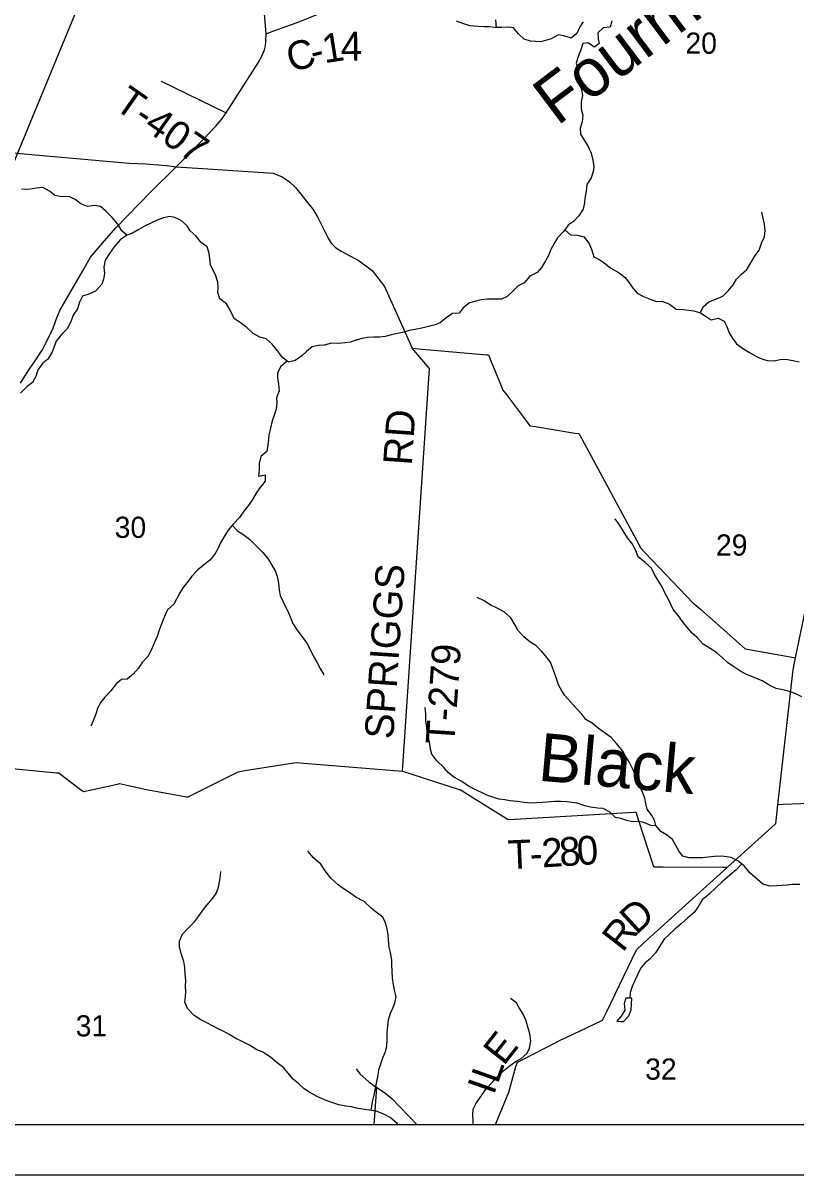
# Model space of a CAD drawing. Extents: x 0 to 34, y 0 to 22.
# Drawn here: x 4.889 to 6.417, y 14 to 16.276 of the extents above; entities that cross this region are included whole.
import ezdxf

# ---------------------------------------------------------------- set-up
doc = ezdxf.new("R2010")
doc.units = 0
for name, color, linetype in [('GM_X_County_Road', 7, 'Continuous'), ('GM_X_County_Road_Text', 7, 'Continuous'), ('GM_X_Minor_Lake', 7, 'Continuous'), ('GM_X_Minor_River', 7, 'Continuous'), ('GM_X_Minor_River_Text', 7, 'Continuous'), ('GM_X_Section_Text', 7, 'Continuous'), ('GM_X_State_Route', 7, 'Continuous'), ('GM_X_Township_Road', 7, 'Continuous'), ('GM_X_Township_Road_Text', 7, 'Continuous'), ('SH_Data', 7, 'Continuous'), ('SH_Text', 7, 'Continuous')]:
    doc.layers.add(name, color=color, linetype=linetype)

msp = doc.modelspace()

# ---------------------------------------------------------------- linework, layer by layer
at = {"layer": 'GM_X_County_Road'}
for points in [[(5.3691, 16.2545), (5.3828, 16.2597), (5.4119, 16.2704), (5.4359, 16.279), (5.4923, 16.3023), (5.5127, 16.3023), (5.6694, 16.2963), (5.6728, 16.2962), (5.686, 16.3055), (5.702, 16.3168), (5.7051, 16.3189), (5.7202, 16.3238), (5.7575, 16.3358), (6.0466, 16.4289), (6.0506, 16.4302), (6.0602, 16.4422), (6.1578, 16.5648), (6.1712, 16.5792), (6.2848, 16.701), (6.2915, 16.7083)], [(5.8229, 14.1), (5.8489, 14.1636), (5.863, 14.2143), (5.8663, 14.2228), (5.8755, 14.2275), (5.9448, 14.2633), (5.9516, 14.2668), (5.9622, 14.2718), (6.0327, 14.3052), (6.0343, 14.3059), (6.042, 14.3219), (6.1012, 14.4448), (6.1155, 14.458), (6.2817, 14.6083), (6.3757, 14.6933), (6.3769, 14.6944), (6.3789, 14.7121), (6.3811, 14.7315), (6.4105, 14.9929), (6.411, 14.9979), (6.414, 15.0121), (6.416, 15.0216), (6.5447, 15.6419)], [(6.6572, 14.1), (6.6653, 14.1868), (6.6656, 14.1893), (6.6487, 14.1925), (6.5516, 14.2109), (6.5544, 14.2302), (6.6345, 14.7411), (6.3911, 14.7319), (6.3811, 14.7315)]]:
    msp.add_lwpolyline(points, dxfattribs=at)
at = {"layer": 'GM_X_Minor_Lake'}
for points in [[(6.0922, 14.3491), (6.0804, 14.3492), (6.0774, 14.3386), (6.0784, 14.3257), (6.0712, 14.3136), (6.0629, 14.3038), (6.0708, 14.3035)], [(6.0708, 14.3035), (6.0761, 14.3033), (6.0864, 14.3147), (6.0909, 14.3264), (6.0922, 14.3491)]]:
    msp.add_lwpolyline(points, dxfattribs=at)
at = {"layer": 'GM_X_Minor_River'}
for points in [[(5.996, 16.2785), (5.9892, 16.2686), (5.9838, 16.2554), (5.9724, 16.246), (5.96, 16.2502), (5.9471, 16.2529), (5.9327, 16.245), (5.9217, 16.2412), (5.9119, 16.239), (5.9017, 16.2394), (5.8918, 16.2402), (5.8797, 16.2444), (5.8684, 16.2547), (5.8586, 16.2665), (5.8477, 16.268), (5.8344, 16.2669), (5.8212, 16.267), (5.8102, 16.2686), (5.8004, 16.2686), (5.7875, 16.269), (5.7717, 16.2706), (5.7584, 16.2752), (5.7456, 16.2798)], [(5.825, 16.267), (5.8235, 16.2822)], [(6.0524, 16.2801), (6.0493, 16.268), (6.0357, 16.2662), (6.0251, 16.2564), (6.0258, 16.245), (6.028, 16.2355), (6.0185, 16.2283), (6.0053, 16.2367), (5.9955, 16.2356), (5.9916, 16.2228), (5.9852, 16.208), (5.9825, 16.1966), (5.9855, 16.1841), (5.9865, 16.167), (5.9876, 16.1572), (5.9925, 16.1447), (5.9947, 16.1325), (5.992, 16.12), (5.9924, 16.1064), (5.9953, 16.0939), (5.9938, 16.0806), (5.9903, 16.0681), (5.991, 16.0563), (5.9978, 16.0442), (6.0057, 16.032), (6.0117, 16.0191), (6.0154, 16.0047), (6.0173, 15.9922), (6.0161, 15.9827), (6.0119, 15.9698), (6.0035, 15.957), (6.0023, 15.943), (5.9996, 15.9301), (5.9985, 15.9206), (5.9962, 15.9081), (5.9878, 15.8949), (5.9768, 15.8835), (5.9669, 15.8771), (5.9567, 15.8635), (5.9456, 15.8518), (5.9395, 15.842), (5.9323, 15.8288), (5.9273, 15.8166), (5.9216, 15.806), (5.914, 15.7932), (5.9049, 15.783), (5.8905, 15.7755), (5.8791, 15.7626), (5.8674, 15.757), (5.8579, 15.7468)], [(5.0937, 15.857), (5.0839, 15.8657), (5.0764, 15.8783), (5.0647, 15.892), (5.0527, 15.9045), (5.0417, 15.9137), (5.03, 15.9156), (5.016, 15.9134), (5.0028, 15.9187), (4.9915, 15.9275), (4.9798, 15.9332), (4.9658, 15.9325), (4.9518, 15.9352), (4.9412, 15.944), (4.928, 15.9509), (4.9147, 15.9498), (4.9004, 15.9468), (4.886, 15.948)], [(5.8579, 15.7468), (5.8457, 15.7355), (5.8347, 15.7306), (5.8207, 15.7302), (5.806, 15.7303), (5.7942, 15.7288), (5.784, 15.7266), (5.7715, 15.7229), (5.759, 15.7134), (5.7506, 15.7028), (5.7378, 15.7018), (5.7249, 15.6938), (5.7131, 15.6833), (5.7033, 15.6795), (5.69, 15.6765), (5.6771, 15.6732), (5.6635, 15.6706), (5.6518, 15.6683), (5.6419, 15.6653), (5.6291, 15.6624), (5.6162, 15.6598), (5.6056, 15.6568), (5.5931, 15.6553), (5.5825, 15.6553), (5.5696, 15.6546), (5.5594, 15.6528), (5.5492, 15.6498), (5.5352, 15.6457), (5.5253, 15.6438), (5.5132, 15.6427), (5.4988, 15.6432), (5.4841, 15.6398), (5.4724, 15.6387), (5.4602, 15.6365), (5.4492, 15.6267), (5.4397, 15.6184), (5.4268, 15.6089), (5.4136, 15.6056), (5.4015, 15.6151), (5.3921, 15.628), (5.3812, 15.6417), (5.3691, 15.652), (5.3566, 15.6551), (5.3438, 15.6627), (5.331, 15.6741), (5.3208, 15.6821), (5.3068, 15.6917), (5.3012, 15.7011), (5.2967, 15.7114), (5.2907, 15.7209), (5.2779, 15.7308), (5.2737, 15.7437), (5.2742, 15.7536), (5.2738, 15.7642), (5.2693, 15.7782), (5.2637, 15.7881), (5.2596, 15.7983), (5.2577, 15.8101), (5.257, 15.8215), (5.2525, 15.8336), (5.2412, 15.8424), (5.2307, 15.8546), (5.2193, 15.8652), (5.213, 15.8751), (5.2013, 15.8861), (5.1888, 15.8919), (5.1782, 15.8934), (5.1661, 15.8912), (5.1536, 15.8867), (5.1411, 15.8803), (5.1301, 15.8754), (5.1165, 15.8671), (5.1036, 15.8604), (5.0937, 15.857), (5.0808, 15.8479), (5.069, 15.8339), (5.0595, 15.8207), (5.0508, 15.8075), (5.0485, 15.7938), (5.0499, 15.7813), (5.048, 15.77), (5.0446, 15.7601), (5.032, 15.7465), (5.0188, 15.7401), (5.0066, 15.7364), (5.0005, 15.7247), (4.9963, 15.711), (4.9876, 15.6986), (4.9834, 15.6853), (4.9758, 15.6717), (4.9647, 15.6607), (4.9541, 15.6475), (4.9495, 15.635), (4.9457, 15.6244), (4.9377, 15.6116), (4.9278, 15.6036), (4.918, 15.5908), (4.9141, 15.5775), (4.9077, 15.5654), (4.897, 15.5575), (4.8837, 15.5447)], [(6.2273, 15.7034), (6.2342, 15.7161), (6.2444, 15.7252), (6.2599, 15.7312), (6.2721, 15.7361), (6.2827, 15.747), (6.2926, 15.7588), (6.2994, 15.7697), (6.3089, 15.7795), (6.3199, 15.789), (6.3256, 15.7988), (6.3348, 15.8147), (6.3439, 15.8275), (6.3489, 15.8408), (6.3542, 15.8533), (6.3561, 15.8658), (6.3543, 15.8783), (6.3521, 15.8901), (6.3495, 15.9022)], [(5.9595, 15.8673), (5.971, 15.8574), (5.985, 15.8566), (5.9975, 15.8535), (6.008, 15.8406), (6.0129, 15.8273), (6.0174, 15.814), (6.0291, 15.8079), (6.04, 15.8003), (6.051, 15.7915), (6.0672, 15.7824), (6.0796, 15.7725), (6.0872, 15.7626), (6.0947, 15.7516), (6.103, 15.742), (6.1154, 15.7356), (6.1283, 15.7306), (6.1408, 15.726), (6.1525, 15.7267), (6.1668, 15.7206), (6.1797, 15.7107), (6.1937, 15.7102), (6.205, 15.7087), (6.2148, 15.7075), (6.2277, 15.7033), (6.2394, 15.696), (6.2492, 15.6896), (6.2628, 15.6929), (6.2745, 15.6872), (6.2798, 15.6762), (6.285, 15.664), (6.2907, 15.6541), (6.299, 15.642), (6.3129, 15.6321), (6.3246, 15.6248), (6.3397, 15.6164), (6.3495, 15.6122), (6.3597, 15.6095), (6.3737, 15.6087), (6.3881, 15.6121), (6.3998, 15.6109), (6.4108, 15.609), (6.4233, 15.6063)], [(5.4106, 15.6079), (5.3984, 15.5973), (5.3916, 15.5848), (5.3915, 15.5753), (5.3938, 15.5624), (5.3948, 15.5495), (5.3899, 15.5355), (5.3902, 15.5257), (5.3894, 15.5132), (5.3844, 15.4995), (5.381, 15.4897), (5.3779, 15.4753), (5.3749, 15.4624), (5.3741, 15.4522), (5.3729, 15.4424), (5.3706, 15.4295), (5.3588, 15.4193), (5.3554, 15.406), (5.3553, 15.3939), (5.3545, 15.3806), (5.3674, 15.3832), (5.3673, 15.3707), (5.3571, 15.3579), (5.3495, 15.3473), (5.3426, 15.3344), (5.3358, 15.3246), (5.3255, 15.3114), (5.3164, 15.2989), (5.305, 15.2868), (5.2943, 15.274), (5.2856, 15.2604), (5.2787, 15.2479), (5.2741, 15.2373), (5.2681, 15.2267), (5.2578, 15.2146), (5.2479, 15.2071), (5.2346, 15.1957), (5.2225, 15.1829), (5.2149, 15.1731), (5.2054, 15.1606), (5.1985, 15.1504), (5.1924, 15.1375), (5.1871, 15.1277), (5.1742, 15.1164), (5.1696, 15.1065), (5.1658, 15.0967), (5.1616, 15.0869), (5.1578, 15.0763), (5.1536, 15.0638), (5.149, 15.0539), (5.1429, 15.0384), (5.1357, 15.0244), (5.1239, 15.0119), (5.1167, 15.001), (5.1064, 14.9897), (5.0946, 14.9798), (5.0837, 14.9787), (5.0734, 14.9708), (5.062, 14.9568), (5.0506, 14.944), (5.0426, 14.9342), (5.0358, 14.9221), (5.0335, 14.9122), (5.0278, 14.8986), (5.0228, 14.8865)], [(6.4284, 14.9448), (6.4163, 14.9509), (6.4042, 14.9551), (6.3906, 14.9582), (6.3778, 14.9613), (6.3664, 14.9666), (6.3498, 14.9762), (6.334, 14.983), (6.3189, 14.9888), (6.3075, 14.9949), (6.2958, 15.0025), (6.2811, 15.0128), (6.2713, 15.022), (6.26, 15.0319), (6.2472, 15.0399), (6.2336, 15.049), (6.2211, 15.0619), (6.2113, 15.0703), (6.1997, 15.084), (6.1925, 15.0935), (6.1846, 15.1049), (6.1741, 15.1175), (6.1696, 15.1273), (6.1647, 15.1372), (6.1575, 15.1501), (6.1523, 15.1619), (6.144, 15.1748), (6.1372, 15.1866), (6.1309, 15.1987), (6.1184, 15.2098), (6.1048, 15.2216), (6.0996, 15.2349), (6.0925, 15.2482), (6.0838, 15.2588), (6.0748, 15.2725), (6.068, 15.2843), (6.0593, 15.2964)], [(5.3023, 15.2836), (5.3125, 15.2724), (5.3231, 15.2659), (5.3366, 15.2564), (5.3487, 15.2438), (5.3619, 15.2305), (5.3724, 15.2183), (5.3807, 15.2047), (5.3879, 15.1925), (5.3912, 15.1826), (5.3938, 15.169), (5.3953, 15.1553), (5.3971, 15.1451), (5.4031, 15.1326), (5.4073, 15.1223), (5.4129, 15.1128), (5.4181, 15.0995), (5.4219, 15.0893), (5.4305, 15.0767), (5.4497, 15.0509), (5.4565, 15.0383), (5.4625, 15.0258), (5.4697, 15.0129), (5.4764, 15.0004), (5.4832, 14.9882)], [(6.3782, 14.5713), (6.3657, 14.5709), (6.351, 14.5748), (6.3404, 14.5835), (6.3257, 14.5972), (6.3141, 14.6105), (6.3016, 14.6208), (6.2888, 14.6273), (6.2699, 14.63), (6.2559, 14.629), (6.2434, 14.6279), (6.2316, 14.6264), (6.2188, 14.6268), (6.2059, 14.6269), (6.1931, 14.6296), (6.1859, 14.6391), (6.1728, 14.663), (6.163, 14.6706), (6.1497, 14.6783), (6.1399, 14.6904), (6.1373, 14.7007), (6.1321, 14.7105), (6.1227, 14.7227), (6.1201, 14.7341), (6.1178, 14.7443), (6.1133, 14.7565), (6.1073, 14.7698), (6.1021, 14.7796), (6.098, 14.7925), (6.0935, 14.8028), (6.0871, 14.8161), (6.0803, 14.826), (6.0743, 14.8374), (6.0622, 14.8526), (6.0513, 14.8644), (6.04, 14.8724), (6.0257, 14.883), (6.0136, 14.8926), (6.0015, 14.8998), (5.9932, 14.9101), (5.9831, 14.9219), (5.9597, 14.947), (5.9541, 14.9565), (5.9473, 14.9686), (5.9439, 14.9785), (5.9398, 14.9903), (5.9361, 15.0009), (5.9312, 15.013), (5.9214, 15.0256), (5.9135, 15.0351), (5.9022, 15.0461), (5.8909, 15.0534), (5.8788, 15.0633), (5.8671, 15.0762), (5.8619, 15.0864), (5.8532, 15.1005), (5.8404, 15.1119), (5.8272, 15.1192), (5.8132, 15.1261), (5.7989, 15.1348), (5.7864, 15.1409)], [(6.1403, 14.69), (6.1301, 14.6905), (6.1158, 14.6962), (6.1059, 14.6981), (6.0934, 14.6974), (6.0825, 14.7005), (6.0704, 14.704), (6.0602, 14.7063), (6.0481, 14.7177), (6.0357, 14.7242), (6.0251, 14.725), (6.0103, 14.7269), (5.9994, 14.7296), (5.9843, 14.7346), (5.9638, 14.7373), (5.951, 14.7382), (5.9396, 14.7378), (5.9252, 14.7367), (5.9154, 14.7356), (5.9041, 14.7353), (5.8927, 14.7346), (5.8791, 14.7358), (5.8662, 14.7381), (5.8515, 14.7393), (5.8409, 14.7412), (5.8303, 14.7428), (5.8194, 14.7459), (5.8054, 14.7505), (5.7789, 14.7638), (5.7691, 14.7684), (5.7559, 14.7776), (5.7404, 14.786), (5.7291, 14.7951), (5.7205, 14.805), (5.7069, 14.8179), (5.6971, 14.8312), (5.6941, 14.8415), (5.6926, 14.8513), (5.6904, 14.8642), (5.6874, 14.8779), (5.6863, 14.8885), (5.6852, 14.898), (5.6849, 14.9105), (5.6838, 14.9238)], [(5.5772, 14.1273), (5.5799, 14.1442), (5.583, 14.1578), (5.5853, 14.1711), (5.588, 14.1847), (5.5907, 14.1972), (5.5923, 14.2078), (5.5965, 14.2214), (5.5999, 14.2313), (5.6045, 14.2419), (5.608, 14.2547), (5.6084, 14.268), (5.6088, 14.2809), (5.6096, 14.2945), (5.6112, 14.3066), (5.615, 14.3199), (5.62, 14.3297), (5.6238, 14.3396), (5.6265, 14.3517), (5.6239, 14.3627), (5.6213, 14.3756), (5.6194, 14.3885), (5.6187, 14.4033), (5.6176, 14.4142), (5.6177, 14.4241), (5.6151, 14.4393), (5.6128, 14.4503), (5.6114, 14.4643), (5.6103, 14.4753), (5.6077, 14.4889), (5.6047, 14.4992), (5.6002, 14.5091), (5.587, 14.5193), (5.5772, 14.5273), (5.5629, 14.5403), (5.5466, 14.5491), (5.5349, 14.5571), (5.5217, 14.5662), (5.5115, 14.5731), (5.4972, 14.5864), (5.4859, 14.6012), (5.4773, 14.6141), (5.4629, 14.6263), (5.452, 14.6396)], [(6.3094, 14.6144), (6.2985, 14.603), (6.286, 14.5921), (6.2708, 14.5793), (6.259, 14.5679), (6.245, 14.5551), (6.2313, 14.5434), (6.2226, 14.5294), (6.2157, 14.5184), (6.2032, 14.5079), (6.1899, 14.4962), (6.177, 14.4856), (6.166, 14.4754), (6.1561, 14.466), (6.147, 14.4516), (6.139, 14.4388), (6.1284, 14.4267), (6.1185, 14.4191), (6.1098, 14.4093), (6.1033, 14.3953), (6.0983, 14.3844), (6.0926, 14.3722), (6.0888, 14.3605), (6.0883, 14.3491)], [(5.2104, 14.3624), (5.21, 14.3722), (5.2105, 14.3851), (5.2094, 14.3976), (5.2087, 14.4097), (5.2064, 14.4215), (5.2016, 14.4374), (5.1982, 14.4511), (5.1983, 14.4621), (5.204, 14.4757), (5.2154, 14.4878), (5.2275, 14.5003), (5.2359, 14.5105), (5.2427, 14.5214), (5.2526, 14.5335), (5.2636, 14.5464), (5.2705, 14.5562), (5.2751, 14.5687), (5.2785, 14.5861), (5.2797, 14.5994)], [(6.4244, 14.5741), (6.4096, 14.5738), (6.3994, 14.5723), (6.3896, 14.572), (6.3782, 14.5713)], [(5.6301, 14.1), (5.6286, 14.1019), (5.6142, 14.1137), (5.6018, 14.1202), (5.587, 14.126), (5.5731, 14.1279), (5.5598, 14.1299), (5.5481, 14.1322), (5.5379, 14.1345), (5.5269, 14.136), (5.5133, 14.1384), (5.4993, 14.143), (5.4846, 14.1483), (5.4703, 14.1548), (5.4555, 14.1632), (5.4446, 14.1701), (5.434, 14.18), (5.4227, 14.1895), (5.4122, 14.2017), (5.4043, 14.2119), (5.3911, 14.2215), (5.3779, 14.2325), (5.3613, 14.2432), (5.3511, 14.247), (5.3363, 14.2565), (5.3209, 14.2645), (5.3095, 14.2699), (5.2974, 14.2768), (5.2857, 14.2836), (5.2756, 14.2882), (5.2635, 14.2947), (5.2533, 14.2997), (5.2404, 14.3065), (5.2268, 14.3149), (5.2137, 14.3286), (5.2088, 14.3415), (5.2096, 14.3518), (5.2104, 14.3624)], [(5.7785, 14.1), (5.7788, 14.1074), (5.7777, 14.1195), (5.7789, 14.1302), (5.7846, 14.1419), (5.7941, 14.1559), (5.8036, 14.1695), (5.8169, 14.1831), (5.8252, 14.1929), (5.8393, 14.2061), (5.8526, 14.217), (5.8636, 14.2246), (5.8734, 14.2302), (5.8856, 14.2404), (5.8902, 14.2506), (5.8928, 14.2642), (5.8906, 14.2787), (5.8865, 14.2927), (5.8828, 14.3056), (5.8775, 14.3174), (5.8696, 14.3299), (5.864, 14.3398), (5.8523, 14.3489)]]:
    msp.add_lwpolyline(points, dxfattribs=at)
at = {"layer": 'GM_X_State_Route'}
msp.add_lwpolyline([(4.8838, 15.5646), (4.8989, 15.5885), (4.9104, 15.6049), (4.9267, 15.6297), (4.9479, 15.6713), (4.9543, 15.6901), (4.9612, 15.7083), (4.969, 15.7205), (5.0099, 15.791), (5.0223, 15.8136), (5.0449, 15.8403), (5.0725, 15.8715), (5.1419, 15.9434), (5.1913, 15.9918), (5.2459, 16.0469), (5.2695, 16.0713), (5.2814, 16.0853), (5.2906, 16.0984), (5.3533, 16.1974), (5.3608, 16.2105), (5.3658, 16.2231), (5.3678, 16.2312), (5.369, 16.2403), (5.3691, 16.2545), (5.3683, 16.2706), (5.3643, 16.3184)], dxfattribs=at)
at = {"layer": 'GM_X_Township_Road'}
for p, q in [((5.1618, 16.1613), (5.2906, 16.0984)), ((5.5829, 14.1), (5.5879, 14.173))]:
    msp.add_line(p, q, dxfattribs=at)
for points in [[(4.7911, 16.0016), (4.8212, 16.0162), (4.8333, 16.0212), (4.8461, 16.0212), (5.0986, 15.999), (5.1312, 15.998), (5.1718, 15.9947)], [(5.1718, 15.9947), (5.1738, 15.9945), (5.1913, 15.9918), (5.2439, 15.9886), (5.383, 15.979), (5.4007, 15.9723), (5.4158, 15.9625), (5.4271, 15.9509), (5.4616, 15.908), (5.4715, 15.8914), (5.4922, 15.8508), (5.4976, 15.8411), (5.5065, 15.8323), (5.5176, 15.8251), (5.5531, 15.8064), (5.5788, 15.7869), (5.6034, 15.7551), (5.6579, 15.6335), (5.6775, 15.6317), (5.8056, 15.6207), (5.8086, 15.6204), (5.815, 15.605), (5.834, 15.5593), (5.8375, 15.5509), (5.8438, 15.5424), (5.8854, 15.4871), (5.8906, 15.4803), (5.9016, 15.4785), (5.9797, 15.4659), (5.9873, 15.4647), (5.9931, 15.4541), (6.1061, 15.2455), (6.1098, 15.2387), (6.1181, 15.23), (6.2138, 15.13), (6.2145, 15.1293), (6.2286, 15.1169), (6.3102, 15.045), (6.3162, 15.0397), (6.3277, 15.0376), (6.4055, 15.0235), (6.416, 15.0216)], [(5.6388, 14.7975), (5.6923, 15.5932), (5.6579, 15.6335)], [(4.8475, 14.8048), (4.9548, 14.7948), (4.9592, 14.7943), (4.9713, 14.7852), (5.0026, 14.7617), (5.0082, 14.7575), (5.0205, 14.7603), (5.0779, 14.7731), (5.0795, 14.7735), (5.097, 14.7696), (5.1352, 14.7612), (5.1398, 14.7602), (5.1545, 14.7574), (5.2122, 14.7468), (5.2138, 14.7465), (5.2299, 14.7545), (5.3087, 14.794), (5.3139, 14.7966), (5.3275, 14.7988), (5.4242, 14.8145), (5.4285, 14.8152), (5.4437, 14.8139), (5.6388, 14.7975), (5.6406, 14.7974), (5.6576, 14.7919), (5.7508, 14.7619), (5.7529, 14.7613), (5.7677, 14.7521), (5.8426, 14.7056), (5.8477, 14.7024), (5.8612, 14.7032), (6.0959, 14.717), (6.1, 14.7172), (6.1048, 14.7025), (6.1353, 14.6095), (6.1356, 14.6086), (6.1543, 14.6086), (6.2718, 14.6083), (6.2817, 14.6083)], [(5.5472, 14.2095), (5.5547, 14.1996), (5.5731, 14.1833), (5.5879, 14.173), (5.6032, 14.1631), (5.6176, 14.151), (5.6674, 14.1)]]:
    msp.add_lwpolyline(points, dxfattribs=at)
at = {"layer": 'SH_Data'}
for p, q in [((2.1, 14.1), (8.9, 14.1)), ((2, 14), (9, 14))]:
    msp.add_line(p, q, dxfattribs=at)
at = {"layer": 'SH_Text'}
msp.add_lwpolyline([(4.7911, 16.5585), (4.7911, 15.8085), (5.3209, 17.091)], close=True, dxfattribs=at)

# ---------------------------------------------------------------- texts
at = {"layer": 'GM_X_County_Road_Text'}
for s, rotation, p in [('1', 9.0243, (5.4846, 16.1963)), ('4', 0.51, (5.517, 16.2016)), ('C', 16.1572, (5.419, 16.1781)), ('-', 13.9208, (5.4633, 16.1909)), ('D', 42.6295, (6.1011, 14.4731)), ('R', 52.3307, (6.0743, 14.4381)), ('E', 51.804, (5.8391, 14.2142)), ('L', 70.4768, (5.8272, 14.1784)), ('I', 70.6431, (5.8195, 14.1565))]:
    msp.add_text(s, height=0.0568, rotation=rotation, dxfattribs=at).set_placement(p)
at = {"layer": 'GM_X_Minor_River_Text'}
for s, rotation, p in [('Fourmile', 37.0021, (5.9447, 16.0715)), ('Black', 354.9973, (5.9052, 14.7793))]:
    msp.add_text(s, height=0.0947, rotation=rotation, dxfattribs=at).set_placement(p)
at = {"layer": 'GM_X_Section_Text'}
for s, p in [('20', (6.1982, 16.2153)), ('30', (5.0699, 15.2587)), ('29', (6.2586, 15.2237)), ('31', (4.9928, 14.2737)), ('32', (6.1186, 14.1883))]:
    msp.add_text(s, height=0.04186, rotation=0, dxfattribs=at).set_placement(p)
at = {"layer": 'GM_X_Township_Road_Text'}
for s, height, rotation, p in [('T-407', 0.05682, 325.0239, (5.0665, 16.1084)), ('RD', 0.05682, 86.0533, (5.6572, 15.401)), ('SPRIGGS', 0.05682, 86.164, (5.6205, 14.8601)), ('T-279', 0.05682, 86.0741, (5.7412, 14.8494)), ('T', 0.0568, 2.4778, (5.8484, 14.6042)), ('2', 0.0568, 3.5666, (5.9154, 14.6075)), ('8', 0.0568, 3.6152, (5.9504, 14.6096)), ('0', 0.0568, 3.6307, (5.9853, 14.6119)), ('-', 0.0568, 3.3939, (5.8919, 14.6061))]:
    msp.add_text(s, height=height, rotation=rotation, dxfattribs=at).set_placement(p)

doc.saveas('drawing.dxf')
